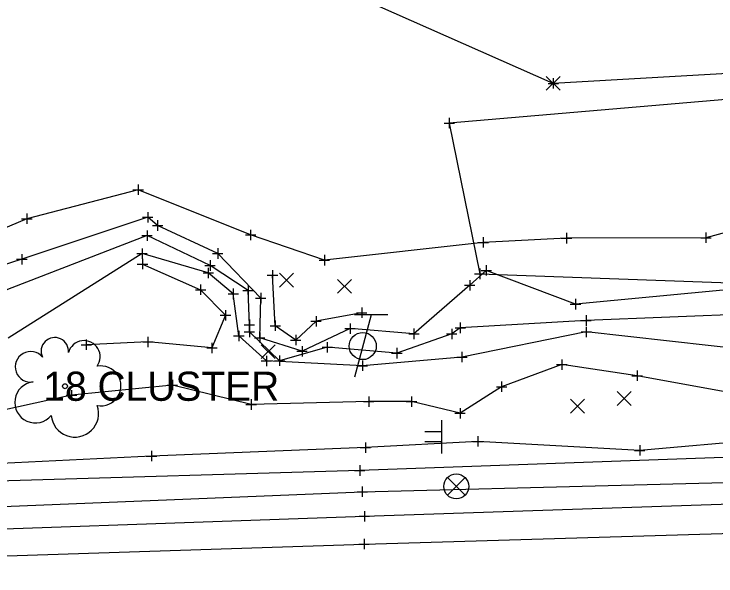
# Model space of a CAD drawing. Extents: x 211013 to 211654, y 505587 to 505872.
# Drawn here: x 211376.6 to 211444.1, y 505734.3 to 505788.3 of the extents above; entities that cross this region are included whole.
import ezdxf

# ---------------------------------------------------------------- set-up
doc = ezdxf.new("R2010")
doc.units = 0
for name, color, linetype in [('AP_P_PCI_Pavement', 7, 'Continuous'), ('CL_X_RW', 7, 'Continuous'), ('DV_X_Section_VMS_Line', 7, 'Continuous'), ('GE_X_Alignment', 7, 'Continuous'), ('GE_X_Alignment_1000_Curve_Data', 7, 'Continuous'), ('GE_X_Alignment_100_Curve_Data', 7, 'Continuous'), ('GE_X_Alignment_100_Stations', 7, 'Continuous'), ('GE_X_Alignment_500_Curve_Data', 7, 'Continuous'), ('GE_X_Alignment_500_Stations', 7, 'Continuous'), ('PM_X_Edge_Line', 7, 'Continuous'), ('RW_P_Esmt_SH', 7, 'Continuous'), ('RW_X_CL_20', 7, 'Continuous'), ('RW_X_Esmt_SH', 7, 'Continuous'), ('SC_Scratch2', 7, 'Continuous'), ('SV_P_Mon_Cells_Set', 7, 'Continuous'), ('SV_X_Control_Cells_Found', 7, 'Continuous'), ('SV_X_Mon_Cells_Found', 7, 'Continuous'), ('VG_X_Text', 7, 'Continuous')]:
    doc.layers.add(name, color=color, linetype=linetype)

msp = doc.modelspace()

# ---------------------------------------------------------------- linework, layer by layer
at = {"layer": 'AP_P_PCI_Pavement'}
for points in [[(211514.705, 505755.709), (211510.87, 505759.501), (211505.589, 505764.016), (211501.024, 505770.994), (211492.8, 505773.47), (211486.118, 505777.367), (211472.166, 505777.575), (211459.37, 505771.193), (211443.099, 505766.813), (211429.688, 505766.767), (211421.675, 505766.362), (211406.416, 505764.649), (211399.312, 505767.08), (211388.509, 505771.416), (211377.8, 505768.628), (211364.654, 505763.097), (211358.872, 505763.944), (211354.313, 505768.086), (211343.281, 505769.575), (211336.593, 505764.394), (211326.759, 505762.682)], [(211514.565, 505754.912), (211509.806, 505750.047), (211506.205, 505749.27), (211491.845, 505756.508), (211484.038, 505756.687), (211472.186, 505755.809), (211464.926, 505755.741), (211447.232, 505751.576), (211436.484, 505753.546), (211429.241, 505754.623), (211423.452, 505752.486), (211419.459, 505749.937), (211414.788, 505751.066), (211410.669, 505751.056), (211399.368, 505750.783), (211391.792, 505752.651), (211382.098, 505751.671), (211364.881, 505747.89)]]:
    msp.add_lwpolyline(points, dxfattribs=at)
at = {"layer": 'CL_X_RW'}
for p, q in [((211410.903, 505759.397), (211409.297, 505753.397)), ((211412.503, 505759.397), (211409.303, 505759.397))]:
    msp.add_line(p, q, dxfattribs=at)
msp.add_circle((211410.1, 505756.397), 1.3, dxfattribs=at)
at = {"layer": 'DV_X_Section_VMS_Line'}
for p, q in [((211427.914, 505781.643), (211428.914, 505781.643)), ((211428.414, 505782.143), (211428.414, 505781.143)), ((211428.414, 505781.643), (211428.414, 505781.643)), ((211418.414, 505778.325), (211418.414, 505777.325)), ((211417.914, 505777.825), (211418.914, 505777.825)), ((211418.414, 505777.825), (211418.414, 505777.825)), ((211388.509, 505771.916), (211388.509, 505770.916)), ((211388.009, 505771.416), (211389.009, 505771.416)), ((211388.509, 505771.416), (211388.509, 505771.416)), ((211377.8, 505769.128), (211377.8, 505768.128)), ((211388.921, 505768.773), (211389.921, 505768.773)), ((211389.421, 505769.273), (211389.421, 505768.273)), ((211389.421, 505768.773), (211389.421, 505768.773)), ((211377.3, 505768.628), (211378.3, 505768.628)), ((211377.8, 505768.628), (211377.8, 505768.628)), ((211390.378, 505768.482), (211390.378, 505767.482)), ((211389.36, 505767.511), (211389.36, 505766.511)), ((211389.878, 505767.982), (211390.878, 505767.982)), ((211390.378, 505767.982), (211390.378, 505767.982)), ((211399.312, 505767.58), (211399.312, 505766.58)), ((211388.86, 505767.011), (211389.86, 505767.011)), ((211389.36, 505767.011), (211389.36, 505767.011)), ((211398.812, 505767.08), (211399.812, 505767.08)), ((211399.312, 505767.08), (211399.312, 505767.08)), ((211421.675, 505766.862), (211421.675, 505765.862)), ((211429.188, 505766.767), (211430.188, 505766.767)), ((211429.688, 505767.267), (211429.688, 505766.267)), ((211429.688, 505766.767), (211429.688, 505766.767)), ((211442.599, 505766.813), (211443.599, 505766.813)), ((211443.099, 505767.313), (211443.099, 505766.313)), ((211443.099, 505766.813), (211443.099, 505766.813)), ((211421.175, 505766.362), (211422.175, 505766.362)), ((211421.675, 505766.362), (211421.675, 505766.362)), ((211388.883, 505765.779), (211388.883, 505764.779)), ((211396.154, 505765.794), (211396.154, 505764.794)), ((211376.824, 505764.741), (211377.824, 505764.741)), ((211377.324, 505765.241), (211377.324, 505764.241)), ((211377.324, 505764.741), (211377.324, 505764.741)), ((211388.383, 505765.279), (211389.383, 505765.279)), ((211388.883, 505765.279), (211388.883, 505765.279)), ((211388.923, 505764.773), (211388.923, 505763.773)), ((211395.654, 505765.294), (211396.654, 505765.294)), ((211396.154, 505765.294), (211396.154, 505765.294)), ((211406.416, 505765.149), (211406.416, 505764.149)), ((211388.423, 505764.273), (211389.423, 505764.273)), ((211388.923, 505764.273), (211388.923, 505764.273)), ((211394.913, 505764.141), (211395.913, 505764.141)), ((211395.413, 505764.641), (211395.413, 505763.641)), ((211395.413, 505764.141), (211395.413, 505764.141)), ((211405.916, 505764.649), (211406.916, 505764.649)), ((211406.416, 505764.649), (211406.416, 505764.649)), ((211421.978, 505764.168), (211421.978, 505763.168)), ((211394.747, 505763.43), (211395.747, 505763.43)), ((211395.247, 505763.93), (211395.247, 505762.93)), ((211395.247, 505763.43), (211395.247, 505763.43)), ((211401.424, 505763.697), (211401.424, 505762.697)), ((211420.841, 505763.342), (211421.841, 505763.342)), ((211421.341, 505763.842), (211421.341, 505762.842)), ((211421.341, 505763.342), (211421.341, 505763.342)), ((211421.478, 505763.668), (211422.478, 505763.668)), ((211421.978, 505763.668), (211421.978, 505763.668)), ((211400.924, 505763.197), (211401.924, 505763.197)), ((211401.424, 505763.197), (211401.424, 505763.197)), ((211420.39, 505762.74), (211420.39, 505761.74)), ((211394.507, 505762.315), (211394.507, 505761.315)), ((211399.072, 505762.237), (211399.072, 505761.237)), ((211419.89, 505762.24), (211420.89, 505762.24)), ((211420.39, 505762.24), (211420.39, 505762.24)), ((211394.007, 505761.815), (211395.007, 505761.815)), ((211394.507, 505761.815), (211394.507, 505761.815)), ((211397.152, 505761.42), (211398.152, 505761.42)), ((211397.652, 505761.92), (211397.652, 505760.92)), ((211397.652, 505761.42), (211397.652, 505761.42)), ((211398.572, 505761.737), (211399.572, 505761.737)), ((211399.072, 505761.737), (211399.072, 505761.737)), ((211400.286, 505761.507), (211400.286, 505760.507)), ((211399.786, 505761.007), (211400.786, 505761.007)), ((211400.286, 505761.007), (211400.286, 505761.007)), ((211430.555, 505760.921), (211430.555, 505759.921)), ((211410.007, 505760.106), (211410.007, 505759.106)), ((211430.055, 505760.421), (211431.055, 505760.421)), ((211430.555, 505760.421), (211430.555, 505760.421)), ((211396.403, 505759.357), (211397.403, 505759.357)), ((211396.903, 505759.857), (211396.903, 505758.857)), ((211396.903, 505759.357), (211396.903, 505759.357)), ((211409.507, 505759.606), (211410.507, 505759.606)), ((211410.007, 505759.606), (211410.007, 505759.606)), ((211431.568, 505759.357), (211431.568, 505758.357)), ((211399.205, 505758.95), (211399.205, 505757.95)), ((211401.69, 505758.858), (211401.69, 505757.858)), ((211405.116, 505758.777), (211406.116, 505758.777)), ((211405.616, 505759.277), (211405.616, 505758.277)), ((211405.616, 505758.777), (211405.616, 505758.777)), ((211419.479, 505758.65), (211419.479, 505757.65)), ((211431.068, 505758.857), (211432.068, 505758.857)), ((211431.568, 505758.857), (211431.568, 505758.857)), ((211398.705, 505758.45), (211399.705, 505758.45)), ((211399.201, 505758.264), (211399.201, 505757.264)), ((211399.205, 505758.45), (211399.205, 505758.45)), ((211401.19, 505758.358), (211402.19, 505758.358)), ((211401.69, 505758.358), (211401.69, 505758.358)), ((211408.378, 505758.074), (211409.378, 505758.074)), ((211408.878, 505758.574), (211408.878, 505757.574)), ((211408.878, 505758.074), (211408.878, 505758.074)), ((211415.024, 505758.076), (211415.024, 505757.076)), ((211418.654, 505758.061), (211418.654, 505757.061)), ((211418.979, 505758.15), (211419.979, 505758.15)), ((211419.479, 505758.15), (211419.479, 505758.15)), ((211431.593, 505758.252), (211431.593, 505757.252)), ((211389.447, 505757.294), (211389.447, 505756.294)), ((211397.685, 505757.371), (211398.685, 505757.371)), ((211398.185, 505757.871), (211398.185, 505756.871)), ((211398.185, 505757.371), (211398.185, 505757.371)), ((211398.701, 505757.764), (211399.701, 505757.764)), ((211399.201, 505757.764), (211399.201, 505757.764)), ((211400.196, 505757.701), (211400.196, 505756.701)), ((211403.654, 505757.469), (211403.654, 505756.469)), ((211414.524, 505757.576), (211415.524, 505757.576)), ((211415.024, 505757.576), (211415.024, 505757.576)), ((211418.154, 505757.561), (211419.154, 505757.561)), ((211418.654, 505757.561), (211418.654, 505757.561)), ((211431.093, 505757.752), (211432.093, 505757.752)), ((211431.593, 505757.752), (211431.593, 505757.752)), ((211383.515, 505757.023), (211383.515, 505756.023)), ((211388.947, 505756.794), (211389.947, 505756.794)), ((211389.447, 505756.794), (211389.447, 505756.794)), ((211395.596, 505756.723), (211395.596, 505755.723)), ((211399.696, 505757.201), (211400.696, 505757.201)), ((211400.196, 505757.201), (211400.196, 505757.201)), ((211403.154, 505756.969), (211404.154, 505756.969)), ((211403.654, 505756.969), (211403.654, 505756.969)), ((211406.691, 505756.787), (211406.691, 505755.787)), ((211383.015, 505756.523), (211384.015, 505756.523)), ((211383.515, 505756.523), (211383.515, 505756.523)), ((211395.096, 505756.223), (211396.096, 505756.223)), ((211395.596, 505756.223), (211395.596, 505756.223)), ((211404.267, 505756.397), (211404.267, 505755.397)), ((211406.191, 505756.287), (211407.191, 505756.287)), ((211406.691, 505756.287), (211406.691, 505756.287)), ((211413.374, 505756.215), (211413.374, 505755.215)), ((211400.837, 505755.47), (211400.837, 505754.47)), ((211402.098, 505755.483), (211402.098, 505754.483)), ((211403.767, 505755.897), (211404.767, 505755.897)), ((211404.267, 505755.897), (211404.267, 505755.897)), ((211412.874, 505755.715), (211413.874, 505755.715)), ((211413.374, 505755.715), (211413.374, 505755.715)), ((211419.133, 505755.343), (211420.133, 505755.343)), ((211419.633, 505755.843), (211419.633, 505754.843)), ((211419.633, 505755.343), (211419.633, 505755.343)), ((211400.337, 505754.97), (211401.337, 505754.97)), ((211400.837, 505754.97), (211400.837, 505754.97)), ((211401.598, 505754.983), (211402.598, 505754.983)), ((211402.098, 505754.983), (211402.098, 505754.983)), ((211410.071, 505755.009), (211410.071, 505754.009)), ((211428.741, 505754.623), (211429.741, 505754.623)), ((211429.241, 505755.123), (211429.241, 505754.123)), ((211429.241, 505754.623), (211429.241, 505754.623)), ((211409.571, 505754.509), (211410.571, 505754.509)), ((211410.071, 505754.509), (211410.071, 505754.509)), ((211436.484, 505754.046), (211436.484, 505753.046)), ((211435.984, 505753.546), (211436.984, 505753.546)), ((211436.484, 505753.546), (211436.484, 505753.546)), ((211391.292, 505752.651), (211392.292, 505752.651)), ((211391.792, 505753.151), (211391.792, 505752.151)), ((211391.792, 505752.651), (211391.792, 505752.651)), ((211423.452, 505752.986), (211423.452, 505751.986)), ((211382.098, 505752.171), (211382.098, 505751.171)), ((211422.952, 505752.486), (211423.952, 505752.486)), ((211423.452, 505752.486), (211423.452, 505752.486)), ((211381.598, 505751.671), (211382.598, 505751.671)), ((211382.098, 505751.671), (211382.098, 505751.671)), ((211399.368, 505751.283), (211399.368, 505750.283)), ((211410.669, 505751.556), (211410.669, 505750.556)), ((211414.788, 505751.566), (211414.788, 505750.566)), ((211398.868, 505750.783), (211399.868, 505750.783)), ((211399.368, 505750.783), (211399.368, 505750.783)), ((211410.169, 505751.056), (211411.169, 505751.056)), ((211410.669, 505751.056), (211410.669, 505751.056)), ((211414.288, 505751.066), (211415.288, 505751.066)), ((211414.788, 505751.066), (211414.788, 505751.066)), ((211418.959, 505749.937), (211419.959, 505749.937)), ((211419.459, 505750.437), (211419.459, 505749.437)), ((211419.459, 505749.937), (211419.459, 505749.937)), ((211410.353, 505747.148), (211410.353, 505746.148)), ((211420.666, 505747.243), (211421.666, 505747.243)), ((211421.166, 505747.743), (211421.166, 505746.743)), ((211421.166, 505747.243), (211421.166, 505747.243)), ((211409.853, 505746.648), (211410.853, 505746.648)), ((211410.353, 505746.648), (211410.353, 505746.648)), ((211436.723, 505746.873), (211436.723, 505745.873)), ((211389.29, 505745.834), (211390.29, 505745.834)), ((211389.79, 505746.334), (211389.79, 505745.334)), ((211389.79, 505745.834), (211389.79, 505745.834)), ((211436.223, 505746.373), (211437.223, 505746.373)), ((211436.723, 505746.373), (211436.723, 505746.373)), ((211409.304, 505744.439), (211410.304, 505744.439)), ((211409.804, 505744.939), (211409.804, 505743.939)), ((211409.804, 505744.439), (211409.804, 505744.439)), ((211410.048, 505742.897), (211410.048, 505741.897)), ((211409.548, 505742.397), (211410.548, 505742.397)), ((211410.048, 505742.397), (211410.048, 505742.397)), ((211410.256, 505740.538), (211410.256, 505739.538)), ((211409.756, 505740.038), (211410.756, 505740.038)), ((211410.256, 505740.038), (211410.256, 505740.038)), ((211410.228, 505737.875), (211410.228, 505736.875)), ((211410.228, 505737.875), (211410.228, 505736.875)), ((211409.728, 505737.375), (211410.728, 505737.375)), ((211409.728, 505737.375), (211410.728, 505737.375)), ((211410.228, 505737.375), (211410.228, 505737.375)), ((211410.228, 505737.375), (211410.228, 505737.375))]:
    msp.add_line(p, q, dxfattribs=at)
at = {"layer": 'GE_X_Alignment'}
msp.add_lwpolyline([(211647.113, 505766.881), (211605.184, 505766.944), (211562.5, 505771.866), (211523.743, 505777.961), (211494.971, 505782.499), (211454.677, 505783.125), (211428.414, 505781.643), (211395.883, 505796.028), (211383.925, 505815.915), (211384.939, 505839.212)], dxfattribs=at)
at = {"layer": 'GE_X_Alignment_1000_Curve_Data'}
msp.add_lwpolyline([(211508.852, 505755.984), (211502, 505758.947), (211492.735, 505762.833), (211484.644, 505768.385), (211473.063, 505773.142), (211465.527, 505768.007), (211460.595, 505767.498), (211447.66, 505759.51), (211431.568, 505758.857), (211419.479, 505758.15), (211418.654, 505757.561), (211413.374, 505755.715), (211406.691, 505756.287), (211402.098, 505754.983), (211399.201, 505757.764), (211399.205, 505758.45), (211399.072, 505761.737), (211395.413, 505764.141), (211389.36, 505767.011), (211375.352, 505761.621)], dxfattribs=at)
at = {"layer": 'GE_X_Alignment_100_Curve_Data'}
msp.add_lwpolyline([(211264.741, 505737.499), (211284.908, 505737.456), (211309.635, 505738.395), (211334.721, 505739.468), (211359.035, 505740.326), (211410.048, 505742.397), (211459.85, 505743.658), (211510.023, 505745.433), (211559.895, 505747.411), (211609.683, 505748.573), (211648.059, 505750.315)], dxfattribs=at)
at = {"layer": 'GE_X_Alignment_100_Stations'}
for points in [[(211388.923, 505764.273), (211394.507, 505761.815), (211396.903, 505759.357), (211395.596, 505756.223), (211389.447, 505756.794), (211383.515, 505756.523)], [(211410.007, 505759.606), (211405.616, 505758.777), (211403.654, 505756.969), (211401.69, 505758.358), (211401.424, 505763.197)], [(211495.14, 505749.377), (211477.211, 505748.988), (211460.001, 505748.41), (211436.723, 505746.373), (211421.166, 505747.243), (211410.353, 505746.648), (211389.79, 505745.834), (211373.994, 505745.063), (211360.301, 505744.106), (211341.963, 505743.211), (211331.272, 505743.043), (211325.122, 505742.455), (211321.974, 505741.027), (211318.886, 505741.328), (211317.045, 505742.571)]]:
    msp.add_lwpolyline(points, dxfattribs=at)
at = {"layer": 'GE_X_Alignment_500_Curve_Data'}
msp.add_lwpolyline([(211014.945, 505724.377), (211059.004, 505725.803), (211109.78, 505727.197), (211159.509, 505728.763), (211208.815, 505730.577), (211259.797, 505732.066), (211285.147, 505733.092), (211309.664, 505733.865), (211334.856, 505734.829), (211359.193, 505735.686), (211410.228, 505737.375), (211459.705, 505738.838), (211509.757, 505740.373), (211559.969, 505741.955), (211609.77, 505743.952), (211648.342, 505745.167)], dxfattribs=at)
at = {"layer": 'GE_X_Alignment_500_Stations'}
msp.add_lwpolyline([(211014.958, 505726.701), (211059.158, 505728.206), (211109.787, 505730.119), (211159.491, 505731.893), (211208.807, 505733.151), (211259.883, 505734.994), (211284.984, 505735.986), (211309.586, 505736.286), (211335.024, 505737.47), (211359.187, 505738.245), (211410.256, 505740.038), (211459.776, 505741.71), (211509.557, 505743.255), (211560.066, 505744.756), (211609.925, 505746.61), (211648.161, 505748.077)], dxfattribs=at)
at = {"layer": 'PM_X_Edge_Line'}
msp.add_lwpolyline([(211014.945, 505724.377), (211059.004, 505725.803), (211109.78, 505727.197), (211159.509, 505728.763), (211208.815, 505730.577), (211259.797, 505732.066), (211285.147, 505733.092), (211309.664, 505733.865), (211334.856, 505734.829), (211359.193, 505735.686), (211410.228, 505737.375), (211459.705, 505738.838), (211509.757, 505740.373), (211559.969, 505741.955), (211609.77, 505743.952), (211648.342, 505745.167)], dxfattribs=at)
at = {"layer": 'RW_P_Esmt_SH'}
for points in [[(211508.408, 505757.764), (211503.869, 505760.503), (211502.223, 505765.549), (211497.583, 505768.543), (211485.324, 505774.712), (211472.783, 505775.364), (211459.92, 505769.461), (211445.428, 505761.831), (211430.555, 505760.421), (211421.978, 505763.668), (211420.39, 505762.24), (211415.024, 505757.576), (211408.878, 505758.074), (211404.267, 505755.897), (211400.196, 505757.201), (211400.286, 505761.007), (211396.154, 505765.294), (211390.378, 505767.982), (211389.421, 505768.773), (211377.324, 505764.741), (211364.894, 505760.758)], [(211508.195, 505754.714), (211503.226, 505753.234), (211496.532, 505756.604), (211485.274, 505761.08), (211473.247, 505761.336), (211463.922, 505760.492), (211447.587, 505755.988), (211431.593, 505757.752), (211419.633, 505755.343), (211410.071, 505754.509), (211400.837, 505754.97), (211398.185, 505757.371), (211397.652, 505761.42), (211395.247, 505763.43), (211388.883, 505765.279), (211375.997, 505757.159)]]:
    msp.add_lwpolyline(points, dxfattribs=at)
at = {"layer": 'RW_X_CL_20'}
msp.add_lwpolyline([(211522.884, 505777.689), (211497.674, 505783.415), (211445.017, 505780.088), (211418.414, 505777.825), (211421.341, 505763.342), (211461.449, 505761.9), (211508.619, 505748.657), (211547.11, 505758.309)], dxfattribs=at)
at = {"layer": 'RW_X_Esmt_SH'}
for p, q in [((211427.747, 505780.976), (211429.081, 505782.311)), ((211427.747, 505782.311), (211429.081, 505780.976)), ((211402.107, 505762.069), (211403.441, 505763.404)), ((211402.107, 505763.404), (211403.441, 505762.069)), ((211407.669, 505761.468), (211409.003, 505762.803)), ((211407.669, 505762.803), (211409.003, 505761.468)), ((211400.346, 505755.191), (211401.68, 505756.526)), ((211400.346, 505756.526), (211401.68, 505755.191)), ((211434.561, 505750.693), (211435.894, 505752.028)), ((211434.561, 505752.028), (211435.894, 505750.693)), ((211430.083, 505749.957), (211431.416, 505751.292)), ((211430.083, 505751.292), (211431.416, 505749.957))]:
    msp.add_line(p, q, dxfattribs=at)
at = {"layer": 'SC_Scratch2'}
for p, q in [((211419.936, 505742.068), (211418.239, 505743.765)), ((211418.239, 505742.068), (211419.936, 505743.765))]:
    msp.add_line(p, q, dxfattribs=at)
msp.add_circle((211419.088, 505742.916), 1.2, dxfattribs=at)
at = {"layer": 'SV_P_Mon_Cells_Set'}
for p, q in [((211417.663, 505749.27), (211417.663, 505746.07)), ((211417.663, 505748.15), (211416.063, 505748.15)), ((211417.663, 505747.19), (211416.063, 505747.19)), ((211417.663, 505747.67), (211417.663, 505747.67))]:
    msp.add_line(p, q, dxfattribs=at)
at = {"layer": 'SV_X_Control_Cells_Found'}
for p, q in [((211460.391, 505746.246), (211409.804, 505744.439)), ((211409.804, 505744.439), (211359.356, 505742.953))]:
    msp.add_line(p, q, dxfattribs=at)
at = {"layer": 'SV_X_Mon_Cells_Found'}
msp.add_circle((211381.474, 505752.539), 0.24, dxfattribs=at)
for centre, radius, start, end in [((211380.491, 505755.907), 1.317, 354.0047, 205.97412), ((211383.3, 505755.368), 1.553, 323.82996, 165.0376), ((211378.165, 505754.403), 1.471, 39.06254, 279.54124), ((211384.935, 505752.575), 1.915, 259.14531, 101.45961), ((211378.621, 505750.99), 1.974, 96.17219, 320.57371), ((211382.421, 505749.934), 2.284, 184.94757, 19.45715)]:
    msp.add_arc(centre, radius, start, end, dxfattribs=at)

# ---------------------------------------------------------------- texts
at = {"layer": 'VG_X_Text'}
msp.add_text('18 CLUSTER', height=2.8, dxfattribs=at).set_placement((211379.391, 505751.139))

doc.saveas('drawing.dxf')
